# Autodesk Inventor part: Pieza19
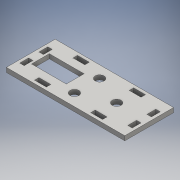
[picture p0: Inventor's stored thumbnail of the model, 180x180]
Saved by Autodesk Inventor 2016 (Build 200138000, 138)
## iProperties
Created: 2016-06
Part Number: Pieza19
Material: Genérico
Document SubType Name: Modeling
Designer: adm
Density: 1 g/cm^3
Appearance: Valor por defecto
Author: adm
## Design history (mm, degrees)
sketch "Boceto1"
  geometry: L1 (35, -11.5)-(-35, 11.5); L2 (-35, -11.5)-(28.913, 9.5); L3 (-40, 16.5)-(40, 16.5); L4 (40, 16.5)-(40, -16.5); L5 (40, -16.5)-(-40, -16.5); L6 (-40, -16.5)-(-40, 16.5); L7 (-15, 14.5)-(-15, 11.5); L8 (-15, -11.5)-(-15, -14.5); L9 (-23, 14.5)-(-23, 11.5); L10 (-23, -11.5)-(-23, -14.5); L11 (23, 14.5)-(23, 11.5); L12 (23, -11.5)-(23, -14.5); L13 (15, 14.5)-(15, 11.5); L14 (15, -11.5)-(15, -14.5); L15 (35, 9.5)-(38, 9.5); L16 (35, 3.5)-(38, 3.5); L17 (35, -3.5)-(38, -3.5); L18 (35, -9.5)-(38, -9.5); L19 (-38, 9.5)-(-35, 9.5); L20 (-38, 3.5)-(-35, 3.5); L21 (-38, -3.5)-(-35, -3.5); L22 (-38, -9.5)-(-35, -9.5); L23 (38, -9.5)-(38, -3.5); L24 (38, 3.5)-(38, 9.5); L25 (35, 9.5)-(35, 3.5); L26 (35, -3.5)-(35, -9.5); L27 (23, 14.5)-(15, 14.5); L28 (-15, 14.5)-(-23, 14.5); L29 (-23, 11.5)-(-15, 11.5); L30 (15, 11.5)-(23, 11.5); L31 (-35, -9.5)-(-35, -3.5); L32 (-35, 3.5)-(-35, 9.5); L33 (-38, 9.5)-(-38, 3.5); L34 (-38, -3.5)-(-38, -9.5); L35 (23, -11.5)-(15, -11.5); L36 (-15, -11.5)-(-23, -11.5); L37 (-23, -14.5)-(-15, -14.5); L38 (15, -14.5)-(23, -14.5); 1 further point
  constraints: 76 end point, 18 parallel, 10 horizontal, 9 perpendicular, 8 vertical, 2 horizontal alignment, 1 midpoint, 1 point on line
  dimensions: "d0" = 70 distance of L1.start L2.start; "d26" = 6 distance of L20.end L19.end; "d27" = 7 distance between parallel lines of L3 L19; "d28" = 6 distance of L16.end L15.end; "d29" = 33 distance between parallel lines of L5 L3; "d30" = 7 distance between parallel lines of L20 L21; "d31" = 7 distance between parallel lines of L5 L22
extrude "Extrusión1" new body sketch "Boceto1" distance "d12" = 3; taper "d13" = 0 deg
sketch "Boceto2"
  geometry: L1 (40, -16.5)-(40, 16.5) reference; L2 (40, 16.5)-(-40, 16.5) reference; L3 (-40, -16.5)-(40, -16.5) reference; L4 (-10, 6)-(-33.5, 6); L5 (-33.5, 6)-(-33.5, -6); L6 (-33.5, -6)-(-10, -6); L7 (-10, -6)-(-10, 6); L8 (35, 3.5)-(35, 9.5) reference; L9 (35, -3.5)-(35, -9.5) reference; L10 (35, -9.5)-(38, -9.5) reference; L11 (15, -11.5)-(23, -11.5) reference; L12 (-15, -11.5)-(-15, -14.5) reference; C1 r 3 at (18, 0); C2 r 3 at (-2, 8.5); C3 r 3 at (-2, -8.5); 2 further points
  constraints: 8 end point, 3 centre point, 2 parallel, 1 horizontal, 1 horizontal alignment, 1 midpoint, 1 perpendicular
  dimensions: "d15" = 6 diameter of C1; "d18" = 6 diameter of C2; "d19" = 6 diameter of C3; "d20" = 23.5 distance of L5.end L6.end; "d21" = 12 distance of L6.end L4.start; "d34" = 17 distance from line of L9 C1.centre; "d38" = 20 horizontal distance of C1.centre C3.centre; "d40" = 20 horizontal distance of C1.centre C2.centre; "d41" = 8 distance from line of C3.centre L7
extrude "Extrusión2" cut sketch "Boceto2" distance "d23" = 3; taper "d24" = 0 deg
node "Sólido1"
other parameters: "d2" = 3, "d3" = 2, "d4" = 8, "d5" = 8, "d6" = 15, "d7" = 15, "d8" = 6, "d9" = 6, "d10" = 3.5, "d11" = 3.5
